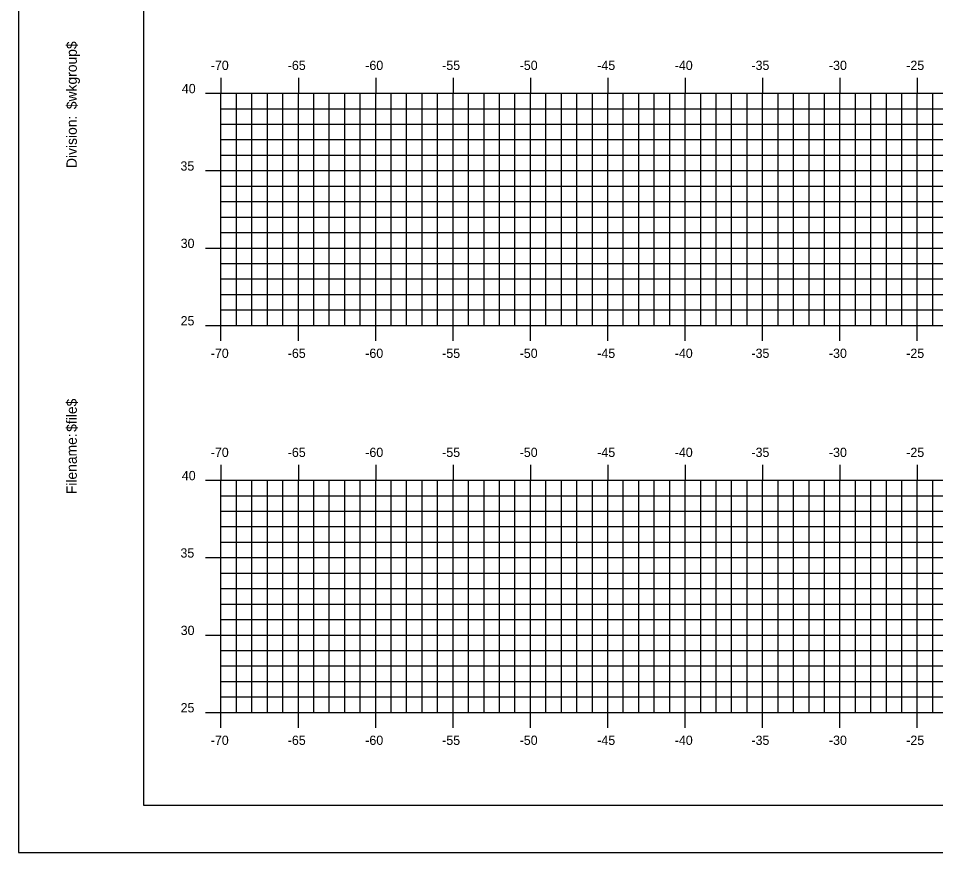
# Model space of a CAD drawing. Extents: x 1026799 to 1026969, y 394697 to 394807.
# Drawn here: x 1026799.3 to 1026858.5, y 394696.5 to 394750.4 of the extents above; entities that cross this region are included whole.
import ezdxf

# ---------------------------------------------------------------- set-up
doc = ezdxf.new("R2010")
doc.units = 0
for name, color, linetype in [('BORDER', 7, 'Continuous'), ('H_V ANNOTATION', 7, 'Continuous'), ('MAJOR', 7, 'Continuous'), ('MINOR', 7, 'Continuous'), ('PLOT BOUNDARY', 7, 'Continuous')]:
    doc.layers.add(name, color=color, linetype=linetype)

msp = doc.modelspace()

# ---------------------------------------------------------------- linework, layer by layer
at = {"layer": 'BORDER'}
for p, q in [((1026807.348, 394804.607), (1026807.348, 394699.607)), ((1026807.348, 394699.607), (1026967.348, 394699.607))]:
    msp.add_line(p, q, dxfattribs=at)
at = {"layer": 'MAJOR'}
for p, q in [((1026812.348, 394746.609), (1026812.348, 394745.607)), ((1026817.348, 394746.609), (1026817.348, 394745.607)), ((1026822.348, 394746.609), (1026822.348, 394745.607)), ((1026827.348, 394746.609), (1026827.348, 394745.607)), ((1026832.348, 394746.609), (1026832.348, 394745.607)), ((1026837.348, 394746.609), (1026837.348, 394745.607)), ((1026842.348, 394746.609), (1026842.348, 394745.607)), ((1026847.348, 394746.609), (1026847.348, 394745.607)), ((1026852.348, 394746.609), (1026852.348, 394745.607)), ((1026857.348, 394746.609), (1026857.348, 394745.607)), ((1026811.346, 394745.607), (1026812.348, 394745.607)), ((1026812.348, 394745.607), (1026952.348, 394745.607)), ((1026812.348, 394730.607), (1026812.348, 394745.607)), ((1026817.348, 394730.607), (1026817.348, 394745.607)), ((1026822.348, 394730.607), (1026822.348, 394745.607)), ((1026827.348, 394730.607), (1026827.348, 394745.607)), ((1026832.348, 394730.607), (1026832.348, 394745.607)), ((1026837.348, 394730.607), (1026837.348, 394745.607)), ((1026842.348, 394730.607), (1026842.348, 394745.607)), ((1026847.348, 394730.607), (1026847.348, 394745.607)), ((1026852.348, 394730.607), (1026852.348, 394745.607)), ((1026857.348, 394730.607), (1026857.348, 394745.607)), ((1026811.346, 394740.607), (1026812.348, 394740.607)), ((1026812.348, 394740.607), (1026952.348, 394740.607)), ((1026811.346, 394735.607), (1026812.348, 394735.607)), ((1026812.348, 394735.607), (1026952.348, 394735.607)), ((1026811.346, 394730.607), (1026812.348, 394730.607)), ((1026812.348, 394730.607), (1026952.348, 394730.607)), ((1026812.348, 394729.605), (1026812.348, 394730.607)), ((1026817.348, 394729.605), (1026817.348, 394730.607)), ((1026822.348, 394729.605), (1026822.348, 394730.607)), ((1026827.348, 394729.605), (1026827.348, 394730.607)), ((1026832.348, 394729.605), (1026832.348, 394730.607)), ((1026837.348, 394729.605), (1026837.348, 394730.607)), ((1026842.348, 394729.605), (1026842.348, 394730.607)), ((1026847.348, 394729.605), (1026847.348, 394730.607)), ((1026852.348, 394729.605), (1026852.348, 394730.607)), ((1026857.348, 394729.605), (1026857.348, 394730.607)), ((1026812.348, 394721.609), (1026812.348, 394720.607)), ((1026817.348, 394721.609), (1026817.348, 394720.607)), ((1026822.348, 394721.609), (1026822.348, 394720.607)), ((1026827.348, 394721.609), (1026827.348, 394720.607)), ((1026832.348, 394721.609), (1026832.348, 394720.607)), ((1026837.348, 394721.609), (1026837.348, 394720.607)), ((1026842.348, 394721.609), (1026842.348, 394720.607)), ((1026847.348, 394721.609), (1026847.348, 394720.607)), ((1026852.348, 394721.609), (1026852.348, 394720.607)), ((1026857.348, 394721.609), (1026857.348, 394720.607)), ((1026811.346, 394720.607), (1026812.348, 394720.607)), ((1026812.348, 394720.607), (1026952.348, 394720.607)), ((1026812.348, 394705.607), (1026812.348, 394720.607)), ((1026817.348, 394705.607), (1026817.348, 394720.607)), ((1026822.348, 394705.607), (1026822.348, 394720.607)), ((1026827.348, 394705.607), (1026827.348, 394720.607)), ((1026832.348, 394705.607), (1026832.348, 394720.607)), ((1026837.348, 394705.607), (1026837.348, 394720.607)), ((1026842.348, 394705.607), (1026842.348, 394720.607)), ((1026847.348, 394705.607), (1026847.348, 394720.607)), ((1026852.348, 394705.607), (1026852.348, 394720.607)), ((1026857.348, 394705.607), (1026857.348, 394720.607)), ((1026811.346, 394715.607), (1026812.348, 394715.607)), ((1026812.348, 394715.607), (1026952.348, 394715.607)), ((1026811.346, 394710.607), (1026812.348, 394710.607)), ((1026812.348, 394710.607), (1026952.348, 394710.607)), ((1026811.346, 394705.607), (1026812.348, 394705.607)), ((1026812.348, 394705.607), (1026952.348, 394705.607)), ((1026812.348, 394704.605), (1026812.348, 394705.607)), ((1026817.348, 394704.605), (1026817.348, 394705.607)), ((1026822.348, 394704.605), (1026822.348, 394705.607)), ((1026827.348, 394704.605), (1026827.348, 394705.607)), ((1026832.348, 394704.605), (1026832.348, 394705.607)), ((1026837.348, 394704.605), (1026837.348, 394705.607)), ((1026842.348, 394704.605), (1026842.348, 394705.607)), ((1026847.348, 394704.605), (1026847.348, 394705.607)), ((1026852.348, 394704.605), (1026852.348, 394705.607)), ((1026857.348, 394704.605), (1026857.348, 394705.607))]:
    msp.add_line(p, q, dxfattribs=at)
at = {"layer": 'MINOR'}
for p, q in [((1026813.348, 394730.607), (1026813.348, 394745.607)), ((1026814.348, 394730.607), (1026814.348, 394745.607)), ((1026815.348, 394730.607), (1026815.348, 394745.607)), ((1026816.348, 394730.607), (1026816.348, 394745.607)), ((1026818.348, 394730.607), (1026818.348, 394745.607)), ((1026819.348, 394730.607), (1026819.348, 394745.607)), ((1026820.348, 394730.607), (1026820.348, 394745.607)), ((1026821.348, 394730.607), (1026821.348, 394745.607)), ((1026823.348, 394730.607), (1026823.348, 394745.607)), ((1026824.348, 394730.607), (1026824.348, 394745.607)), ((1026825.348, 394730.607), (1026825.348, 394745.607)), ((1026826.348, 394730.607), (1026826.348, 394745.607)), ((1026828.348, 394730.607), (1026828.348, 394745.607)), ((1026829.348, 394730.607), (1026829.348, 394745.607)), ((1026830.348, 394730.607), (1026830.348, 394745.607)), ((1026831.348, 394730.607), (1026831.348, 394745.607)), ((1026833.348, 394730.607), (1026833.348, 394745.607)), ((1026834.348, 394730.607), (1026834.348, 394745.607)), ((1026835.348, 394730.607), (1026835.348, 394745.607)), ((1026836.348, 394730.607), (1026836.348, 394745.607)), ((1026838.348, 394730.607), (1026838.348, 394745.607)), ((1026839.348, 394730.607), (1026839.348, 394745.607)), ((1026840.348, 394730.607), (1026840.348, 394745.607)), ((1026841.348, 394730.607), (1026841.348, 394745.607)), ((1026843.348, 394730.607), (1026843.348, 394745.607)), ((1026844.348, 394730.607), (1026844.348, 394745.607)), ((1026845.348, 394730.607), (1026845.348, 394745.607)), ((1026846.348, 394730.607), (1026846.348, 394745.607)), ((1026848.348, 394730.607), (1026848.348, 394745.607)), ((1026849.348, 394730.607), (1026849.348, 394745.607)), ((1026850.348, 394730.607), (1026850.348, 394745.607)), ((1026851.348, 394730.607), (1026851.348, 394745.607)), ((1026853.348, 394730.607), (1026853.348, 394745.607)), ((1026854.348, 394730.607), (1026854.348, 394745.607)), ((1026855.348, 394730.607), (1026855.348, 394745.607)), ((1026856.348, 394730.607), (1026856.348, 394745.607)), ((1026858.348, 394730.607), (1026858.348, 394745.607)), ((1026812.348, 394744.607), (1026952.348, 394744.607)), ((1026812.348, 394744.607), (1026813.35, 394744.607)), ((1026812.348, 394743.607), (1026952.348, 394743.607)), ((1026812.348, 394743.607), (1026813.35, 394743.607)), ((1026812.348, 394742.607), (1026952.348, 394742.607)), ((1026812.348, 394742.607), (1026813.35, 394742.607)), ((1026812.348, 394741.607), (1026952.348, 394741.607)), ((1026812.348, 394741.607), (1026813.35, 394741.607)), ((1026812.348, 394739.607), (1026952.348, 394739.607)), ((1026812.348, 394739.607), (1026813.35, 394739.607)), ((1026812.348, 394738.607), (1026952.348, 394738.607)), ((1026812.348, 394738.607), (1026813.35, 394738.607)), ((1026812.348, 394737.607), (1026952.348, 394737.607)), ((1026812.348, 394737.607), (1026813.35, 394737.607)), ((1026812.348, 394736.607), (1026952.348, 394736.607)), ((1026812.348, 394736.607), (1026813.35, 394736.607)), ((1026812.348, 394734.607), (1026952.348, 394734.607)), ((1026812.348, 394734.607), (1026813.35, 394734.607)), ((1026812.348, 394733.607), (1026952.348, 394733.607)), ((1026812.348, 394733.607), (1026813.35, 394733.607)), ((1026812.348, 394732.607), (1026952.348, 394732.607)), ((1026812.348, 394732.607), (1026813.35, 394732.607)), ((1026812.348, 394731.607), (1026952.348, 394731.607)), ((1026812.348, 394731.607), (1026813.35, 394731.607)), ((1026813.348, 394705.607), (1026813.348, 394720.607)), ((1026814.348, 394705.607), (1026814.348, 394720.607)), ((1026815.348, 394705.607), (1026815.348, 394720.607)), ((1026816.348, 394705.607), (1026816.348, 394720.607)), ((1026818.348, 394705.607), (1026818.348, 394720.607)), ((1026819.348, 394705.607), (1026819.348, 394720.607)), ((1026820.348, 394705.607), (1026820.348, 394720.607)), ((1026821.348, 394705.607), (1026821.348, 394720.607)), ((1026823.348, 394705.607), (1026823.348, 394720.607)), ((1026824.348, 394705.607), (1026824.348, 394720.607)), ((1026825.348, 394705.607), (1026825.348, 394720.607)), ((1026826.348, 394705.607), (1026826.348, 394720.607)), ((1026828.348, 394705.607), (1026828.348, 394720.607)), ((1026829.348, 394705.607), (1026829.348, 394720.607)), ((1026830.348, 394705.607), (1026830.348, 394720.607)), ((1026831.348, 394705.607), (1026831.348, 394720.607)), ((1026833.348, 394705.607), (1026833.348, 394720.607)), ((1026834.348, 394705.607), (1026834.348, 394720.607)), ((1026835.348, 394705.607), (1026835.348, 394720.607)), ((1026836.348, 394705.607), (1026836.348, 394720.607)), ((1026838.348, 394705.607), (1026838.348, 394720.607)), ((1026839.348, 394705.607), (1026839.348, 394720.607)), ((1026840.348, 394705.607), (1026840.348, 394720.607)), ((1026841.348, 394705.607), (1026841.348, 394720.607)), ((1026843.348, 394705.607), (1026843.348, 394720.607)), ((1026844.348, 394705.607), (1026844.348, 394720.607)), ((1026845.348, 394705.607), (1026845.348, 394720.607)), ((1026846.348, 394705.607), (1026846.348, 394720.607)), ((1026848.348, 394705.607), (1026848.348, 394720.607)), ((1026849.348, 394705.607), (1026849.348, 394720.607)), ((1026850.348, 394705.607), (1026850.348, 394720.607)), ((1026851.348, 394705.607), (1026851.348, 394720.607)), ((1026853.348, 394705.607), (1026853.348, 394720.607)), ((1026854.348, 394705.607), (1026854.348, 394720.607)), ((1026855.348, 394705.607), (1026855.348, 394720.607)), ((1026856.348, 394705.607), (1026856.348, 394720.607)), ((1026858.348, 394705.607), (1026858.348, 394720.607)), ((1026812.348, 394719.607), (1026952.348, 394719.607)), ((1026812.348, 394719.607), (1026813.35, 394719.607)), ((1026812.348, 394718.607), (1026952.348, 394718.607)), ((1026812.348, 394718.607), (1026813.35, 394718.607)), ((1026812.348, 394717.607), (1026952.348, 394717.607)), ((1026812.348, 394717.607), (1026813.35, 394717.607)), ((1026812.348, 394716.607), (1026952.348, 394716.607)), ((1026812.348, 394716.607), (1026813.35, 394716.607)), ((1026812.348, 394714.607), (1026952.348, 394714.607)), ((1026812.348, 394714.607), (1026813.35, 394714.607)), ((1026812.348, 394713.607), (1026952.348, 394713.607)), ((1026812.348, 394713.607), (1026813.35, 394713.607)), ((1026812.348, 394712.607), (1026952.348, 394712.607)), ((1026812.348, 394712.607), (1026813.35, 394712.607)), ((1026812.348, 394711.607), (1026952.348, 394711.607)), ((1026812.348, 394711.607), (1026813.35, 394711.607)), ((1026812.348, 394709.607), (1026952.348, 394709.607)), ((1026812.348, 394709.607), (1026813.35, 394709.607)), ((1026812.348, 394708.607), (1026952.348, 394708.607)), ((1026812.348, 394708.607), (1026813.35, 394708.607)), ((1026812.348, 394707.607), (1026952.348, 394707.607)), ((1026812.348, 394707.607), (1026813.35, 394707.607)), ((1026812.348, 394706.607), (1026952.348, 394706.607)), ((1026812.348, 394706.607), (1026813.35, 394706.607))]:
    msp.add_line(p, q, dxfattribs=at)
at = {"layer": 'PLOT BOUNDARY'}
msp.add_lwpolyline([(1026799.254, 394696.548), (1026969.254, 394696.548), (1026969.254, 394806.548), (1026799.254, 394806.548)], close=True, dxfattribs=at)

# ---------------------------------------------------------------- texts
at = {"layer": 'BORDER'}
for s, p in [('$wkgroup$', (1026803.033, 394744.576)), ('Division:', (1026803.033, 394740.773)), ('$file$', (1026803.033, 394723.732)), ('Filename:', (1026803.033, 394719.705))]:
    msp.add_text(s, height=0.6696, rotation=90, dxfattribs=at).set_placement(p)
at = {"layer": 'H_V ANNOTATION'}
for s, p in [('-70', (1026811.689, 394747.107)), ('-65', (1026816.665, 394747.107)), ('-60', (1026821.673, 394747.107)), ('-55', (1026826.644, 394747.107)), ('-50', (1026831.652, 394747.107)), ('-45', (1026836.665, 394747.107)), ('-40', (1026841.673, 394747.107)), ('-35', (1026846.628, 394747.107)), ('-30', (1026851.636, 394747.107)), ('-25', (1026856.633, 394747.107)), ('40', (1026809.82, 394745.607)), ('35', (1026809.729, 394740.607)), ('30', (1026809.745, 394735.607)), ('25', (1026809.74, 394730.607)), ('-70', (1026811.689, 394728.507)), ('-65', (1026816.665, 394728.507)), ('-60', (1026821.673, 394728.507)), ('-55', (1026826.644, 394728.507)), ('-50', (1026831.652, 394728.507)), ('-45', (1026836.665, 394728.507)), ('-40', (1026841.673, 394728.507)), ('-35', (1026846.628, 394728.507)), ('-30', (1026851.636, 394728.507)), ('-25', (1026856.633, 394728.507)), ('-70', (1026811.689, 394722.107)), ('-65', (1026816.665, 394722.107)), ('-60', (1026821.673, 394722.107)), ('-55', (1026826.644, 394722.107)), ('-50', (1026831.652, 394722.107)), ('-45', (1026836.665, 394722.107)), ('-40', (1026841.673, 394722.107)), ('-35', (1026846.628, 394722.107)), ('-30', (1026851.636, 394722.107)), ('-25', (1026856.633, 394722.107)), ('40', (1026809.82, 394720.607)), ('35', (1026809.729, 394715.607)), ('30', (1026809.745, 394710.607)), ('25', (1026809.74, 394705.607)), ('-70', (1026811.689, 394703.507)), ('-65', (1026816.665, 394703.507)), ('-60', (1026821.673, 394703.507)), ('-55', (1026826.644, 394703.507)), ('-50', (1026831.652, 394703.507)), ('-45', (1026836.665, 394703.507)), ('-40', (1026841.673, 394703.507)), ('-35', (1026846.628, 394703.507)), ('-30', (1026851.636, 394703.507)), ('-25', (1026856.633, 394703.507))]:
    msp.add_text(s, height=0.6, dxfattribs=at).set_placement(p)

doc.saveas('drawing.dxf')
